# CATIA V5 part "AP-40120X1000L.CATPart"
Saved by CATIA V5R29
Part number: AP-40120X1000L
Source: Unknown
Bounding box of the stored display mesh (mm): x -500 to 500, y -60 to 60, z -20 to 20
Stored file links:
  C:\가치같이\SmartFactory_BoxErectorConveyor\Boxing(under)\AP-40120X1000L.CATPart
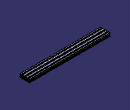
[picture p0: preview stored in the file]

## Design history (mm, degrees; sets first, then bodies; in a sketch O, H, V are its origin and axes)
Body1 (main body)
  Solid1 "PartBody": solid without history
